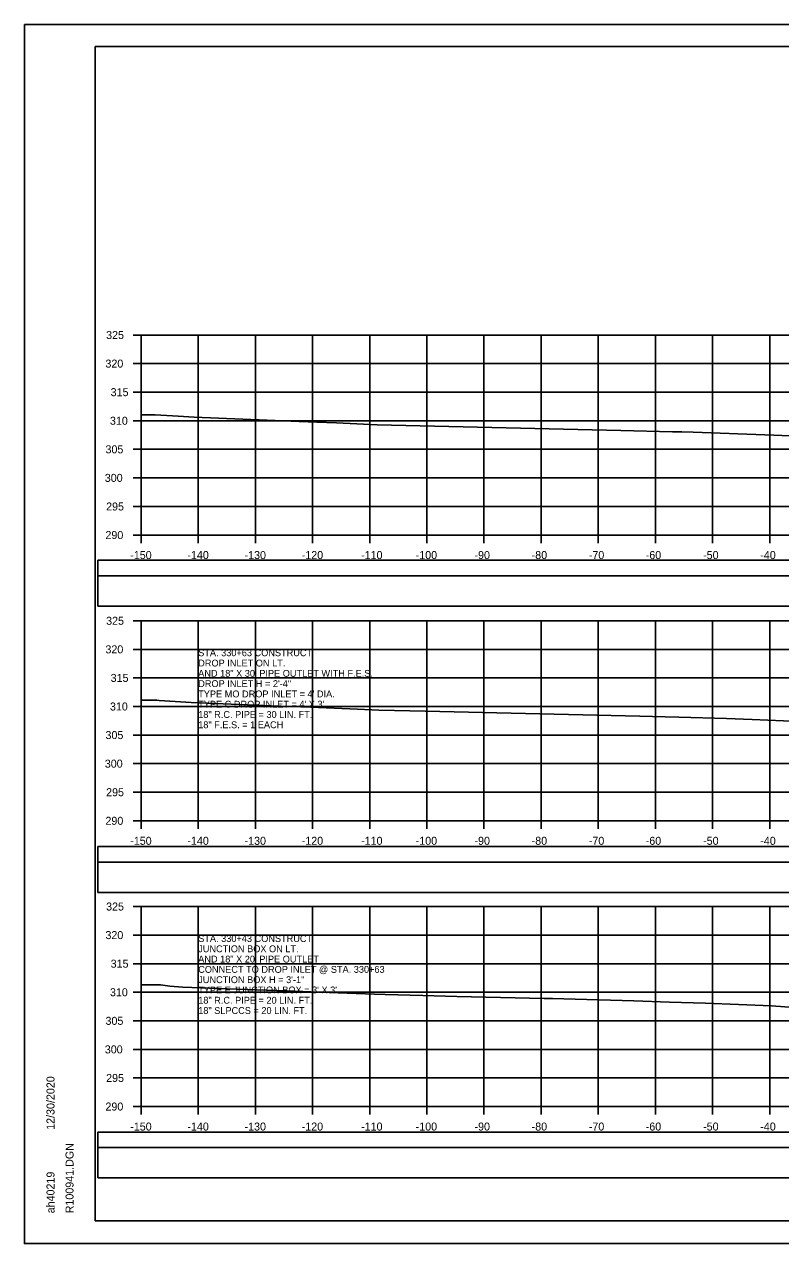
# Model space of a CAD drawing. Extents: x 1370538 to 1372872, y 376220 to 381127.
# Drawn here: x 1372538.2 to 1372670.5, y 378049.2 to 378262.5 of the extents above; entities that cross this region are included whole.
import ezdxf

# ---------------------------------------------------------------- set-up
doc = ezdxf.new("R2010")
doc.units = 0
for name, color, linetype in [('R_Border Notes', 7, 'Continuous'), ('R_Border PE', 7, 'Continuous'), ('R_Border Prem', 7, 'Continuous'), ('R_Dimension', 7, 'Continuous'), ('R_Grid', 7, 'Continuous'), ('R_Horz Alg Annot', 7, 'Continuous'), ('R_No Plot', 7, 'Continuous'), ('R_Water Annot', 7, 'Continuous')]:
    doc.layers.add(name, color=color, linetype=linetype)

msp = doc.modelspace()

# ---------------------------------------------------------------- linework, layer by layer
at = {"layer": 'R_Border Notes'}
for p, q in [((1372550.65, 378258.65), (1372866.83, 378258.65)), ((1372550.65, 378053.19), (1372550.65, 378258.65)), ((1372550.65, 378053.19), (1372550.65, 378053.19)), ((1372866.83, 378053.19), (1372550.65, 378053.19))]:
    msp.add_line(p, q, dxfattribs=at)
at = {"layer": 'R_Border Prem'}
for p, q in [((1372557.25, 378208.19), (1372558.65, 378208.19)), ((1372558.65, 378173.19), (1372558.65, 378208.19)), ((1372557.25, 378203.19), (1372558.65, 378203.19)), ((1372557.25, 378198.19), (1372558.65, 378198.19)), ((1372557.25, 378193.19), (1372558.65, 378193.19)), ((1372557.25, 378188.19), (1372558.65, 378188.19)), ((1372557.25, 378183.19), (1372558.65, 378183.19)), ((1372557.25, 378178.19), (1372558.65, 378178.19)), ((1372557.25, 378173.19), (1372558.65, 378173.19)), ((1372558.65, 378173.19), (1372858.65, 378173.19)), ((1372558.65, 378171.79), (1372558.65, 378173.19)), ((1372568.65, 378171.79), (1372568.65, 378173.19)), ((1372578.65, 378171.79), (1372578.65, 378173.19)), ((1372588.65, 378171.79), (1372588.65, 378173.19)), ((1372598.65, 378171.79), (1372598.65, 378173.19)), ((1372608.65, 378171.79), (1372608.65, 378173.19)), ((1372618.65, 378171.79), (1372618.65, 378173.19)), ((1372628.65, 378171.79), (1372628.65, 378173.19)), ((1372638.65, 378171.79), (1372638.65, 378173.19)), ((1372648.65, 378171.79), (1372648.65, 378173.19)), ((1372658.65, 378171.79), (1372658.65, 378173.19)), ((1372668.65, 378171.79), (1372668.65, 378173.19)), ((1372557.25, 378158.19), (1372558.65, 378158.19)), ((1372558.65, 378123.19), (1372558.65, 378158.19)), ((1372557.25, 378153.19), (1372558.65, 378153.19)), ((1372557.25, 378148.19), (1372558.65, 378148.19)), ((1372557.25, 378143.19), (1372558.65, 378143.19)), ((1372557.25, 378138.19), (1372558.65, 378138.19)), ((1372557.25, 378133.19), (1372558.65, 378133.19)), ((1372557.25, 378128.19), (1372558.65, 378128.19)), ((1372557.25, 378123.19), (1372558.65, 378123.19)), ((1372558.65, 378123.19), (1372858.65, 378123.19)), ((1372558.65, 378121.79), (1372558.65, 378123.19)), ((1372568.65, 378121.79), (1372568.65, 378123.19)), ((1372578.65, 378121.79), (1372578.65, 378123.19)), ((1372588.65, 378121.79), (1372588.65, 378123.19)), ((1372598.65, 378121.79), (1372598.65, 378123.19)), ((1372608.65, 378121.79), (1372608.65, 378123.19)), ((1372618.65, 378121.79), (1372618.65, 378123.19)), ((1372628.65, 378121.79), (1372628.65, 378123.19)), ((1372638.65, 378121.79), (1372638.65, 378123.19)), ((1372648.65, 378121.79), (1372648.65, 378123.19)), ((1372658.65, 378121.79), (1372658.65, 378123.19)), ((1372668.65, 378121.79), (1372668.65, 378123.19)), ((1372557.25, 378108.19), (1372558.65, 378108.19)), ((1372558.65, 378073.19), (1372558.65, 378108.19)), ((1372557.25, 378103.19), (1372558.65, 378103.19)), ((1372557.25, 378098.19), (1372558.65, 378098.19)), ((1372557.25, 378093.19), (1372558.65, 378093.19)), ((1372557.25, 378088.19), (1372558.65, 378088.19)), ((1372557.25, 378083.19), (1372558.65, 378083.19)), ((1372557.25, 378078.19), (1372558.65, 378078.19)), ((1372557.25, 378073.19), (1372558.65, 378073.19)), ((1372558.65, 378073.19), (1372858.65, 378073.19)), ((1372558.65, 378071.79), (1372558.65, 378073.19)), ((1372568.65, 378071.79), (1372568.65, 378073.19)), ((1372578.65, 378071.79), (1372578.65, 378073.19)), ((1372588.65, 378071.79), (1372588.65, 378073.19)), ((1372598.65, 378071.79), (1372598.65, 378073.19)), ((1372608.65, 378071.79), (1372608.65, 378073.19)), ((1372618.65, 378071.79), (1372618.65, 378073.19)), ((1372628.65, 378071.79), (1372628.65, 378073.19)), ((1372638.65, 378071.79), (1372638.65, 378073.19)), ((1372648.65, 378071.79), (1372648.65, 378073.19)), ((1372658.65, 378071.79), (1372658.65, 378073.19)), ((1372668.65, 378071.79), (1372668.65, 378073.19))]:
    msp.add_line(p, q, dxfattribs=at)
at = {"layer": 'R_Dimension'}
for points in [[(1372558.65, 378194.22), (1372561.14, 378194.21), (1372565.14, 378194), (1372567.96, 378193.81), (1372580.72, 378193.31), (1372586.32, 378193.07), (1372589.42, 378192.96), (1372592.84, 378192.8), (1372599.98, 378192.48), (1372642.61, 378191.48), (1372651.63, 378191.27), (1372652.69, 378191.24), (1372653.26, 378191.23), (1372655.27, 378191.17), (1372669.35, 378190.65), (1372673.59, 378190.49)], [(1372558.65, 378144.3), (1372558.91, 378144.3), (1372561.4, 378144.29), (1372561.84, 378144.26), (1372567.41, 378143.87), (1372581.39, 378143.33), (1372588.33, 378143.07), (1372596.54, 378142.73), (1372600.26, 378142.56), (1372608.39, 378142.37), (1372645.93, 378141.49), (1372650.34, 378141.38), (1372652.72, 378141.31), (1372661.06, 378141.07), (1372665.55, 378140.9), (1372673.77, 378140.59)], [(1372558.65, 378094.5), (1372562.04, 378094.5), (1372563.7, 378094.26), (1372565.94, 378094.05), (1372575.32, 378093.72), (1372584.19, 378093.41), (1372588.38, 378093.26), (1372599.48, 378092.83), (1372601.35, 378092.78), (1372607.95, 378092.61), (1372613.92, 378092.47), (1372629.19, 378092.11), (1372630.63, 378092.07), (1372634.59, 378091.98), (1372644.87, 378091.7), (1372651.1, 378091.46), (1372657.42, 378091.27), (1372668.98, 378090.83), (1372678.33, 378090.1)]]:
    msp.add_lwpolyline(points, dxfattribs=at)
at = {"layer": 'R_Grid'}
for p, q in [((1372558.65, 378208.19), (1372858.65, 378208.19)), ((1372558.65, 378173.19), (1372558.65, 378208.19)), ((1372568.65, 378173.19), (1372568.65, 378208.19)), ((1372578.65, 378173.19), (1372578.65, 378208.19)), ((1372588.65, 378173.19), (1372588.65, 378208.19)), ((1372598.65, 378173.19), (1372598.65, 378208.19)), ((1372608.65, 378173.19), (1372608.65, 378208.19)), ((1372618.65, 378173.19), (1372618.65, 378208.19)), ((1372628.65, 378173.19), (1372628.65, 378208.19)), ((1372638.65, 378173.19), (1372638.65, 378208.19)), ((1372648.65, 378173.19), (1372648.65, 378208.19)), ((1372658.65, 378173.19), (1372658.65, 378208.19)), ((1372668.65, 378173.19), (1372668.65, 378208.19)), ((1372558.65, 378203.19), (1372858.65, 378203.19)), ((1372558.65, 378198.19), (1372858.65, 378198.19)), ((1372558.65, 378193.19), (1372858.65, 378193.19)), ((1372558.65, 378188.19), (1372858.65, 378188.19)), ((1372558.65, 378183.19), (1372858.65, 378183.19)), ((1372558.65, 378178.19), (1372858.65, 378178.19)), ((1372558.65, 378173.19), (1372858.65, 378173.19)), ((1372558.65, 378158.19), (1372858.65, 378158.19)), ((1372558.65, 378123.19), (1372558.65, 378158.19)), ((1372568.65, 378123.19), (1372568.65, 378158.19)), ((1372578.65, 378123.19), (1372578.65, 378158.19)), ((1372588.65, 378123.19), (1372588.65, 378158.19)), ((1372598.65, 378123.19), (1372598.65, 378158.19)), ((1372608.65, 378123.19), (1372608.65, 378158.19)), ((1372618.65, 378123.19), (1372618.65, 378158.19)), ((1372628.65, 378123.19), (1372628.65, 378158.19)), ((1372638.65, 378123.19), (1372638.65, 378158.19)), ((1372648.65, 378123.19), (1372648.65, 378158.19)), ((1372658.65, 378123.19), (1372658.65, 378158.19)), ((1372668.65, 378123.19), (1372668.65, 378158.19)), ((1372558.65, 378153.19), (1372858.65, 378153.19)), ((1372558.65, 378148.19), (1372858.65, 378148.19)), ((1372558.65, 378143.19), (1372858.65, 378143.19)), ((1372558.65, 378138.19), (1372858.65, 378138.19)), ((1372558.65, 378133.19), (1372858.65, 378133.19)), ((1372558.65, 378128.19), (1372858.65, 378128.19)), ((1372558.65, 378123.19), (1372858.65, 378123.19)), ((1372558.65, 378108.19), (1372858.65, 378108.19)), ((1372558.65, 378073.19), (1372558.65, 378108.19)), ((1372568.65, 378073.19), (1372568.65, 378108.19)), ((1372578.65, 378073.19), (1372578.65, 378108.19)), ((1372588.65, 378073.19), (1372588.65, 378108.19)), ((1372598.65, 378073.19), (1372598.65, 378108.19)), ((1372608.65, 378073.19), (1372608.65, 378108.19)), ((1372618.65, 378073.19), (1372618.65, 378108.19)), ((1372628.65, 378073.19), (1372628.65, 378108.19)), ((1372638.65, 378073.19), (1372638.65, 378108.19)), ((1372648.65, 378073.19), (1372648.65, 378108.19)), ((1372658.65, 378073.19), (1372658.65, 378108.19)), ((1372668.65, 378073.19), (1372668.65, 378108.19)), ((1372558.65, 378103.19), (1372858.65, 378103.19)), ((1372558.65, 378098.19), (1372858.65, 378098.19)), ((1372558.65, 378093.19), (1372858.65, 378093.19)), ((1372558.65, 378088.19), (1372858.65, 378088.19)), ((1372558.65, 378083.19), (1372858.65, 378083.19)), ((1372558.65, 378078.19), (1372858.65, 378078.19)), ((1372558.65, 378073.19), (1372858.65, 378073.19))]:
    msp.add_line(p, q, dxfattribs=at)
at = {"layer": 'R_Horz Alg Annot'}
for points in [[(1372551.09, 378166.07), (1372866.22, 378166.07), (1372866.22, 378168.78), (1372551.09, 378168.78)], [(1372551.09, 378160.75), (1372866.22, 378160.75), (1372866.22, 378166.07), (1372551.09, 378166.07)], [(1372551.09, 378115.98), (1372866.22, 378115.98), (1372866.22, 378118.69), (1372551.09, 378118.69)], [(1372551.09, 378110.66), (1372866.22, 378110.66), (1372866.22, 378115.98), (1372551.09, 378115.98)], [(1372551.09, 378066.01), (1372866.22, 378066.01), (1372866.22, 378068.71), (1372551.09, 378068.71)], [(1372551.09, 378060.69), (1372866.22, 378060.69), (1372866.22, 378066.01), (1372551.09, 378066.01)]]:
    msp.add_lwpolyline(points, close=True, dxfattribs=at)
at = {"layer": 'R_No Plot'}
for p, q in [((1372538.25, 378262.54), (1372871.58, 378262.54)), ((1372538.25, 378049.21), (1372871.58, 378049.21))]:
    msp.add_line(p, q, dxfattribs=at)
for points in [[(1372538.24, 378262.54), (1372871.58, 378262.54), (1372871.58, 378049.21), (1372538.24, 378049.21)], [(1372784.57, 378258.65), (1372784.57, 378248.77), (1372820.3, 378248.77), (1372820.3, 378245.85), (1372843.5, 378245.85), (1372843.5, 378221.52), (1372866.83, 378221.52), (1372866.83, 378053.19), (1372550.65, 378053.19), (1372550.65, 378258.65)]]:
    msp.add_lwpolyline(points, close=True, dxfattribs=at)

# ---------------------------------------------------------------- texts
at = {"layer": 'R_Border Notes'}
for s, p in [('12/30/2020', (1372543.51, 378069.12)), ('R100941.DGN', (1372546.84, 378054.51)), ('ah40219', (1372543.51, 378054.51))]:
    msp.add_text(s, height=1.4, rotation=90, dxfattribs=at).set_placement(p)
at = {"layer": 'R_Border PE'}
for s, p in [('325', (1372552.54, 378207.49)), ('320', (1372552.42, 378202.49)), ('315', (1372553.33, 378197.49)), ('310', (1372553.21, 378192.49)), ('305', (1372552.43, 378187.49)), ('300', (1372552.31, 378182.49)), ('295', (1372552.54, 378177.49)), ('290', (1372552.42, 378172.49)), ('-150', (1372556.76, 378168.99)), ('-140', (1372566.76, 378168.99)), ('-130', (1372576.76, 378168.99)), ('-120', (1372586.76, 378168.99)), ('-110', (1372597.15, 378168.99)), ('-100', (1372606.7, 378168.99)), ('-90', (1372616.99, 378168.99)), ('-80', (1372626.99, 378168.99)), ('-70', (1372636.99, 378168.99)), ('-60', (1372646.95, 378168.99)), ('-50', (1372656.99, 378168.99)), ('-40', (1372666.99, 378168.99)), ('325', (1372552.54, 378157.49)), ('320', (1372552.42, 378152.49)), ('315', (1372553.33, 378147.49)), ('310', (1372553.21, 378142.49)), ('305', (1372552.43, 378137.49)), ('300', (1372552.31, 378132.49)), ('295', (1372552.54, 378127.49)), ('290', (1372552.42, 378122.49)), ('-150', (1372556.76, 378118.99)), ('-140', (1372566.76, 378118.99)), ('-130', (1372576.76, 378118.99)), ('-120', (1372586.76, 378118.99)), ('-110', (1372597.15, 378118.99)), ('-100', (1372606.7, 378118.99)), ('-90', (1372616.99, 378118.99)), ('-80', (1372626.99, 378118.99)), ('-70', (1372636.99, 378118.99)), ('-60', (1372646.95, 378118.99)), ('-50', (1372656.99, 378118.99)), ('-40', (1372666.99, 378118.99)), ('325', (1372552.54, 378107.49)), ('320', (1372552.42, 378102.49)), ('315', (1372553.33, 378097.49)), ('310', (1372553.21, 378092.49)), ('305', (1372552.43, 378087.49)), ('300', (1372552.31, 378082.49)), ('295', (1372552.54, 378077.49)), ('290', (1372552.42, 378072.49)), ('-150', (1372556.76, 378068.99)), ('-140', (1372566.76, 378068.99)), ('-130', (1372576.76, 378068.99)), ('-120', (1372586.76, 378068.99)), ('-110', (1372597.15, 378068.99)), ('-100', (1372606.7, 378068.99)), ('-90', (1372616.99, 378068.99)), ('-80', (1372626.99, 378068.99)), ('-70', (1372636.99, 378068.99)), ('-60', (1372646.95, 378068.99)), ('-50', (1372656.99, 378068.99)), ('-40', (1372666.99, 378068.99))]:
    msp.add_text(s, height=1.4, dxfattribs=at).set_placement(p)
at = {"layer": 'R_Water Annot'}
for s, p in [('STA. 330+63 CONSTRUCT', (1372568.65, 378151.99)), ('AND 18" X 30\' PIPE OUTLET WITH F.E.S.', (1372568.65, 378148.39)), ('DROP INLET ON LT.', (1372568.65, 378150.19)), ('DROP INLET H = 2\'-4"', (1372568.65, 378146.59)), ("TYPE MO DROP INLET = 4' DIA.", (1372568.65, 378144.79)), ("TYPE C DROP INLET = 4' X 3'", (1372568.65, 378142.99)), ('18" R.C. PIPE = 30 LIN. FT.', (1372568.65, 378141.19)), ('18" F.E.S. = 1 EACH', (1372568.65, 378139.39)), ('STA. 330+43 CONSTRUCT', (1372568.65, 378101.99)), ('JUNCTION BOX ON LT.', (1372568.65, 378100.19)), ('AND 18" X 20\' PIPE OUTLET', (1372568.65, 378098.39)), ('CONNECT TO DROP INLET @ STA. 330+63', (1372568.65, 378096.59)), ('JUNCTION BOX H = 3\'-1"', (1372568.65, 378094.79)), ("TYPE E JUNCTION BOX = 3' X 3'", (1372568.65, 378092.99)), ('18" R.C. PIPE = 20 LIN. FT.', (1372568.65, 378091.19)), ('18" SLPCCS = 20 LIN. FT.', (1372568.65, 378089.39))]:
    msp.add_text(s, height=1.2, dxfattribs=at).set_placement(p)

doc.saveas('drawing.dxf')
